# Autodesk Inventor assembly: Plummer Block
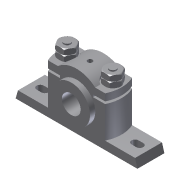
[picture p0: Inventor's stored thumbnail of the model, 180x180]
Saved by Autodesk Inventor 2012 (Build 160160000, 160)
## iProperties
Created: 2011-07
Part Number: Plummer Block
Document SubType Name: Assembly
Designer: CadCim
Author: CadCim
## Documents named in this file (7)
- C:\Users\CadCim\Documents\SAILESH\inventor-2011-fact-prt\c09_inv_2012_prt\Tutorials\c09_tut02_inv\Plummer Block\Plummer Block.iam
- C:\Users\CadCim\Documents\SAILESH\inventor-2011-fact-prt\c09_inv_2012_prt\Tutorials\c09_tut02_inv\Plummer Block\Casting.ipt
- C:\Users\CadCim\Documents\SAILESH\inventor-2011-fact-prt\c09_inv_2012_prt\Tutorials\c09_tut02_inv\Plummer Block\Brasses.ipt
- C:\Users\CadCim\Documents\SAILESH\inventor-2011-fact-prt\c09_inv_2012_prt\Tutorials\c09_tut02_inv\Plummer Block\Cap.ipt
- C:\Users\CadCim\Documents\SAILESH\inventor-2011-fact-prt\c09_inv_2012_prt\Tutorials\c09_tut02_inv\Plummer Block\Bolt.ipt
- C:\Users\CadCim\Documents\SAILESH\inventor-2011-fact-prt\c09_inv_2012_prt\Tutorials\c09_tut02_inv\Plummer Block\Nut.ipt
- C:\Users\CadCim\Documents\SAILESH\inventor-2011-fact-prt\c09_inv_2012_prt\Tutorials\c09_tut02_inv\Plummer Block\Lock Nut.ipt
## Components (9 placed, 6 different names)
1. Casting:1 — Mate:1, Mate:2, Insert:1, Insert:2, Angle:1, Angle:2
2. Brasses:1 — Mate:1, Mate:2, Mate:3, Mate:4
3. Cap:1 — Mate:3, Mate:4, Insert:3, Insert:4
4. Bolt:1 — Insert:1, Angle:1
5. Bolt:2 — Insert:2, Angle:2
6. Nut:1 — Insert:3, Insert:6
7. Nut:2 — Insert:4, Insert:5
8. Lock Nut:1 — Insert:6
9. Lock Nut:2 — Insert:5
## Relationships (12: Insert 6, Mate 4, Angle 2)
- Mate:1: Casting:1 ↔ Brasses:1
- Mate:2: Casting:1 ↔ Brasses:1
- Mate:3: Brasses:1 ↔ Cap:1
- Mate:4: Brasses:1 ↔ Cap:1
- Insert:1: Casting:1 ↔ Bolt:1
- Insert:2: Casting:1 ↔ Bolt:2
- Angle:1: Casting:1 ↔ Bolt:1
- Angle:2: Casting:1 ↔ Bolt:2
- Insert:3: Cap:1 ↔ Nut:1
- Insert:4: Cap:1 ↔ Nut:2
- Insert:5: Nut:2 ↔ Lock Nut:2
- Insert:6: Nut:1 ↔ Lock Nut:1
